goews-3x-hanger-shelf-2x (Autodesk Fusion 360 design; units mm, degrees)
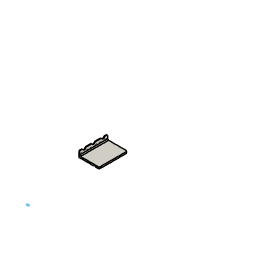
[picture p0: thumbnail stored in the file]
base_feature "Base Feature2"
base_feature "Base Feature1" bodies "Triple Plate Blank"
delete_face "DeleteFace1"
split "Split1" bodies "Triple Plate Blank (1)"
delete_face "DeleteFace2"
move_face "MoveFace1"
fillet "Fillet1" radius 3.75
combine "Combine1" bodies "Triple Plate Blank"
chamfer "Chamfer1" distance 4
move_face "MoveFace2"
extrude "Extrude1" cut sketch "Reconstructed-Sketch2" blind -1060
named bodies: "Triple Plate Blank", "Triple Plate Blank (1)"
